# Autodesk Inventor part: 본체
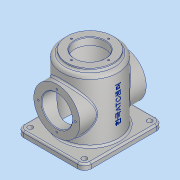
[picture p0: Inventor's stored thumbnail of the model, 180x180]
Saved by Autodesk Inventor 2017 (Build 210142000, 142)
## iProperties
Part Number: 본체
Material: 알루미늄 6061
Document SubType Name: Modeling
Designer: MRC
Density: 2.7 g/cm^3
Appearance: 알루미늄 - 평지
Mass: 1235.44 g
Surface Area: 1067.55 cm^2
Volume: 457.572 cm^3
Author: MRC
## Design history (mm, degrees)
sketch "스케치1"
  geometry: C1 r 50 at (0, 0); 1 further point
  constraints: 1 centre point, 1 coincident
  dimensions: "d0" = 100 diameter of C1
extrude "돌출1" new body sketch "스케치1" stored distance "d1" = 120; taper "d2" = 0 deg
sketch "스케치5"
  geometry: C1 r 50 at (0, 0) reference; C2 r 41 at (0, 0)
  constraints: 1 centre point, 1 coincident
  dimensions: "d17" = 82 diameter of C2
extrude "돌출4" join sketch "스케치5" distance "d18" = 5; taper "d19" = 0 deg
sketch "스케치6"
  geometry: L1 (70, -60)-(-70, -60); L2 (-70, -60)-(-70, 60); L3 (-70, 60)-(70, 60); L4 (70, 60)-(70, -60); L5 (70, -60)-(-70, 60); L6 (-70, -60)-(70, 60); 1 further point
  constraints: 12 end point, 2 midpoint, 2 parallel, 1 horizontal, 1 perpendicular
  dimensions: "d20" = 140 distance of L2.end L3.end; "d21" = 120 distance of L1.end L2.end
extrude "돌출5" join sketch "스케치6" distance "d22" = 10; taper "d23" = 0 deg
node "작업 평면1"
sketch "스케치7"
  geometry: C1 r 41 at (0, 0); 1 further point
  constraints: 1 centre point, 1 coincident
  dimensions: "d25" = 82 diameter of C1
extrude "돌출6" join sketch "스케치7" stored distance "d26" = 10; taper "d27" = 0 deg
sketch "스케치8"
  geometry: 2 further points
  constraints: 1 coincident
hole "구멍2" sketch "스케치8" at (0, 0) diameter "d28" = 54; stored, may be unused: countersink angle "d32" = 90 deg, drill point angle "d34" = 0 deg; dims "d29" = 6, "d30" = 84, "d31" = 112, "d33" = 8
sketch "스케치9"
  geometry: C1 r 27 at (0, 0); 1 further point
  constraints: 1 centre point, 1 coincident
  dimensions: "d35" = 54 diameter of C1
extrude "돌출7" cut sketch "스케치9" stored distance "d36" = 10; taper "d37" = 0 deg
sketch "스케치10"
  geometry: 2 further points
  constraints: 1 vertical alignment
  dimensions: "d38" = 33 distance of point (0, 0) point (0, 33)
hole "구멍3" sketch "스케치10" at (0, 33) diameter "d39" = 3.242; stored, may be unused: countersink angle "d43" = 90 deg, drill point angle "d45" = 118 deg; dims "d40" = 8, "d41" = 84, "d42" = 112, "d44" = 10
sketch "스케치11"
  geometry: 2 further points
  constraints: 1 vertical alignment
  dimensions: "d46" = 33 distance of point (0, 0) point (0, 33)
hole "구멍4" sketch "스케치11" at (0, 33) diameter "d47" = 3.242; stored, may be unused: countersink angle "d51" = 90 deg, drill point angle "d53" = 118 deg; dims "d48" = 8, "d49" = 84, "d50" = 112, "d52" = 10
fillet "모깎기1" dims "d60" = 12
fillet "모깎기2" dims "d61" = 3
fillet "모깎기3" dims "d62" = 6
fillet "모깎기4" dims "d63" = 3
fillet "모깎기5" dims "d64" = 3
sketch "스케치12"
  geometry: C1 r 4.5 at (-58, 48); A1 r 12 centre (-58, 48) between (-58, 60) and (-70, 48) reference; 1 further point
  constraints: 1 centre point, 1 concentric
  dimensions: "d65" = 9 diameter of C1
extrude "돌출8" cut sketch "스케치12" stored distance "d66" = 10; taper "d67" = 0 deg
node "작업 평면2"
sketch "스케치13"
  geometry: L1 (-58, -60)-(58, -60) reference; 2 further points
  constraints: 1 vertical alignment, 1 other
  dimensions: "d69" = 66 distance from line of point (0, 6) L1
feature "엠보싱1" sketch "스케치13" dims "d25" = 82, "d70" = 0.5, "d71" = 0
chamfer "모따기1" distance "d72" = 1; stored, may be unused: second distance "d73" = 2, angle "d74" = 45 deg
node "솔리드1"
pattern_circular "원형 패턴1" dims angle "d55" = 360 deg
pattern_circular "원형 패턴2" dims angle "d58" = 360 deg
mirror "미러1"
mirror "미러2"
mirror "미러3"
other parameters: "d24" = 59
